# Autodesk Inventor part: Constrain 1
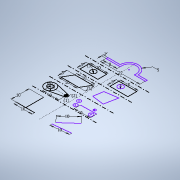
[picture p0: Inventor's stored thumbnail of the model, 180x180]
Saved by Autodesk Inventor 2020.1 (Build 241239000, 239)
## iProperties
Created: 2018-03
Part Number: Constrain 1
Material: Generic
Document SubType Name: Modeling
Designer: DUL
Density: 1 g/cm^3
Appearance: Default
Author: DUL
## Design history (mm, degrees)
sketch "Sketch1"
  geometry: L1 (-14.542, 2.317)-(-4.542, 2.317) reference; L2 (6.154, 3.448)-(13.548, 10.181); L3 (-9.542, 2.317)-(-9.542, 12.317) reference; L4 (5.715, 1.723)-(15.66, 2.773); L5 (-18.13, 14.671)-(18.13, 14.671) reference; L6 (-12.948, 19.414)-(-3.948, 19.414) reference; L7 (-12.281, 22.339)-(-3.725, 20.389) reference; L8 (-12.281, 16.49)-(-3.725, 18.439); L9 (4.516, 18.816)-(13.515, 18.991); L10 (-18.13, 24.076)-(18.13, 24.076) reference; L11 (-14.542, 26.88)-(-11.645, 31.88); L12 (-11.645, 31.88)-(-1.645, 31.88) reference; L13 (-1.645, 31.88)-(-4.542, 26.88) reference; L14 (-4.542, 26.88)-(-14.542, 26.88); L15 (3.663, 26.523)-(4.516, 31.88); L16 (4.516, 31.88)-(11.818, 32.954); L17 (11.818, 32.954)-(10.352, 25.622); L18 (10.352, 25.622)-(3.663, 26.523); L19 (-18.13, 34.382)-(18.13, 34.382) reference; L20 (-13.093, 41.103)-(-3.093, 41.103) reference; L21 (-3.093, 41.103)-(-3.093, 36.103) reference; L22 (-3.093, 36.103)-(-13.093, 36.103); L23 (-13.093, 36.103)-(-13.093, 41.103); L24 (3.663, 41.103)-(13.663, 41.103) reference; L25 (13.663, 41.103)-(13.663, 36.103) reference; L26 (13.663, 36.103)-(3.663, 36.103); L27 (3.663, 36.103)-(3.663, 41.103); L28 (0, 0)-(0, 53.782); L29 (-18.13, 44.046)-(18.13, 44.046) reference; L30 (-10.84, 49.476)-(-3.967, 49.476); L31 (6.033, 49.476)-(11.16, 49.476); L32 (-10.84, 48.476)-(-2.84, 48.476); L33 (4.906, 48.476)-(11.16, 48.476); L34 (-10.84, 49.476)-(-10.84, 48.476); L35 (11.16, 49.476)-(11.16, 48.476); C1 r 1.5 at (-12.948, 19.414) reference; C2 r 0.5 at (-3.948, 19.414) reference; C3 r 1.027 at (2.135, 20.389); C4 r 1.058 at (3.163, 17.465); C5 r 0.669 at (10.866, 20.389); C6 r 1.153 at (12.082, 17.217); C7 r 1.5 at (-8.093, 38.603) reference; C8 r 1.5 at (6.815, 38.948); A1 r 3 centre (-12.948, 19.414) between (-12.281, 22.339) and (-12.281, 16.49) reference; A2 r 1 centre (-3.948, 19.414) between (-3.725, 20.389) and (-3.725, 18.439); A3 r 5 centre (1.033, 49.476) between (6.033, 49.476) and (-3.967, 49.476); A4 r 4 centre (1.033, 49.476) between (4.906, 48.476) and (-2.84, 48.476); 1 further point
  constraints: 70 end point, 18 horizontal, 12 centre point, 8 point on circle, 7 vertical, 5 parallel, 4 tangent, 3 coincident, 3 point on line, 2 midpoint, 2 perpendicular, 1 vertical alignment, 8 other
  dimensions: "d1" = 10 distance of L1.start L1.end; "d4" = 10 distance of L2.start L2.end; "d6" = 10 vertical distance of L1.start L3.end; "d7" = 10 distance of L4.start L4.end; "d13" = 9 distance of L6.start L6.end; "d15" = 6 diameter of A1 (derived); "d16" = 3 diameter of C1 (derived); "d17" = 2 diameter of A2 (derived); "d18" = 1 diameter of C2 (derived); "d21" = 9 distance of L9.start L9.end; "d22" = 10 distance of L13.end L11.start; "d23" = 5 vertical distance of L11.start L11.end; "d24" = 10 distance of L11.end L12.end; "d25" = 5 vertical distance of L12.end L13.end (derived); "d26" = 10 distance of L20.start L20.end; "d27" = 5 distance of L22.end L20.start; "d29" = 3 diameter of C7 (derived); "d30" = 10 distance of L24.start L24.end; "d31" = 5 distance of L26.end L24.start; "d32" = 3 diameter of C8; "d33" = 1 distance between parallel lines of L30 L32; "d34" = 5 radius of A3; "d35" = 8 distance of L32.start L32.end; "d37" = 22 distance between parallel lines of L35 L34
